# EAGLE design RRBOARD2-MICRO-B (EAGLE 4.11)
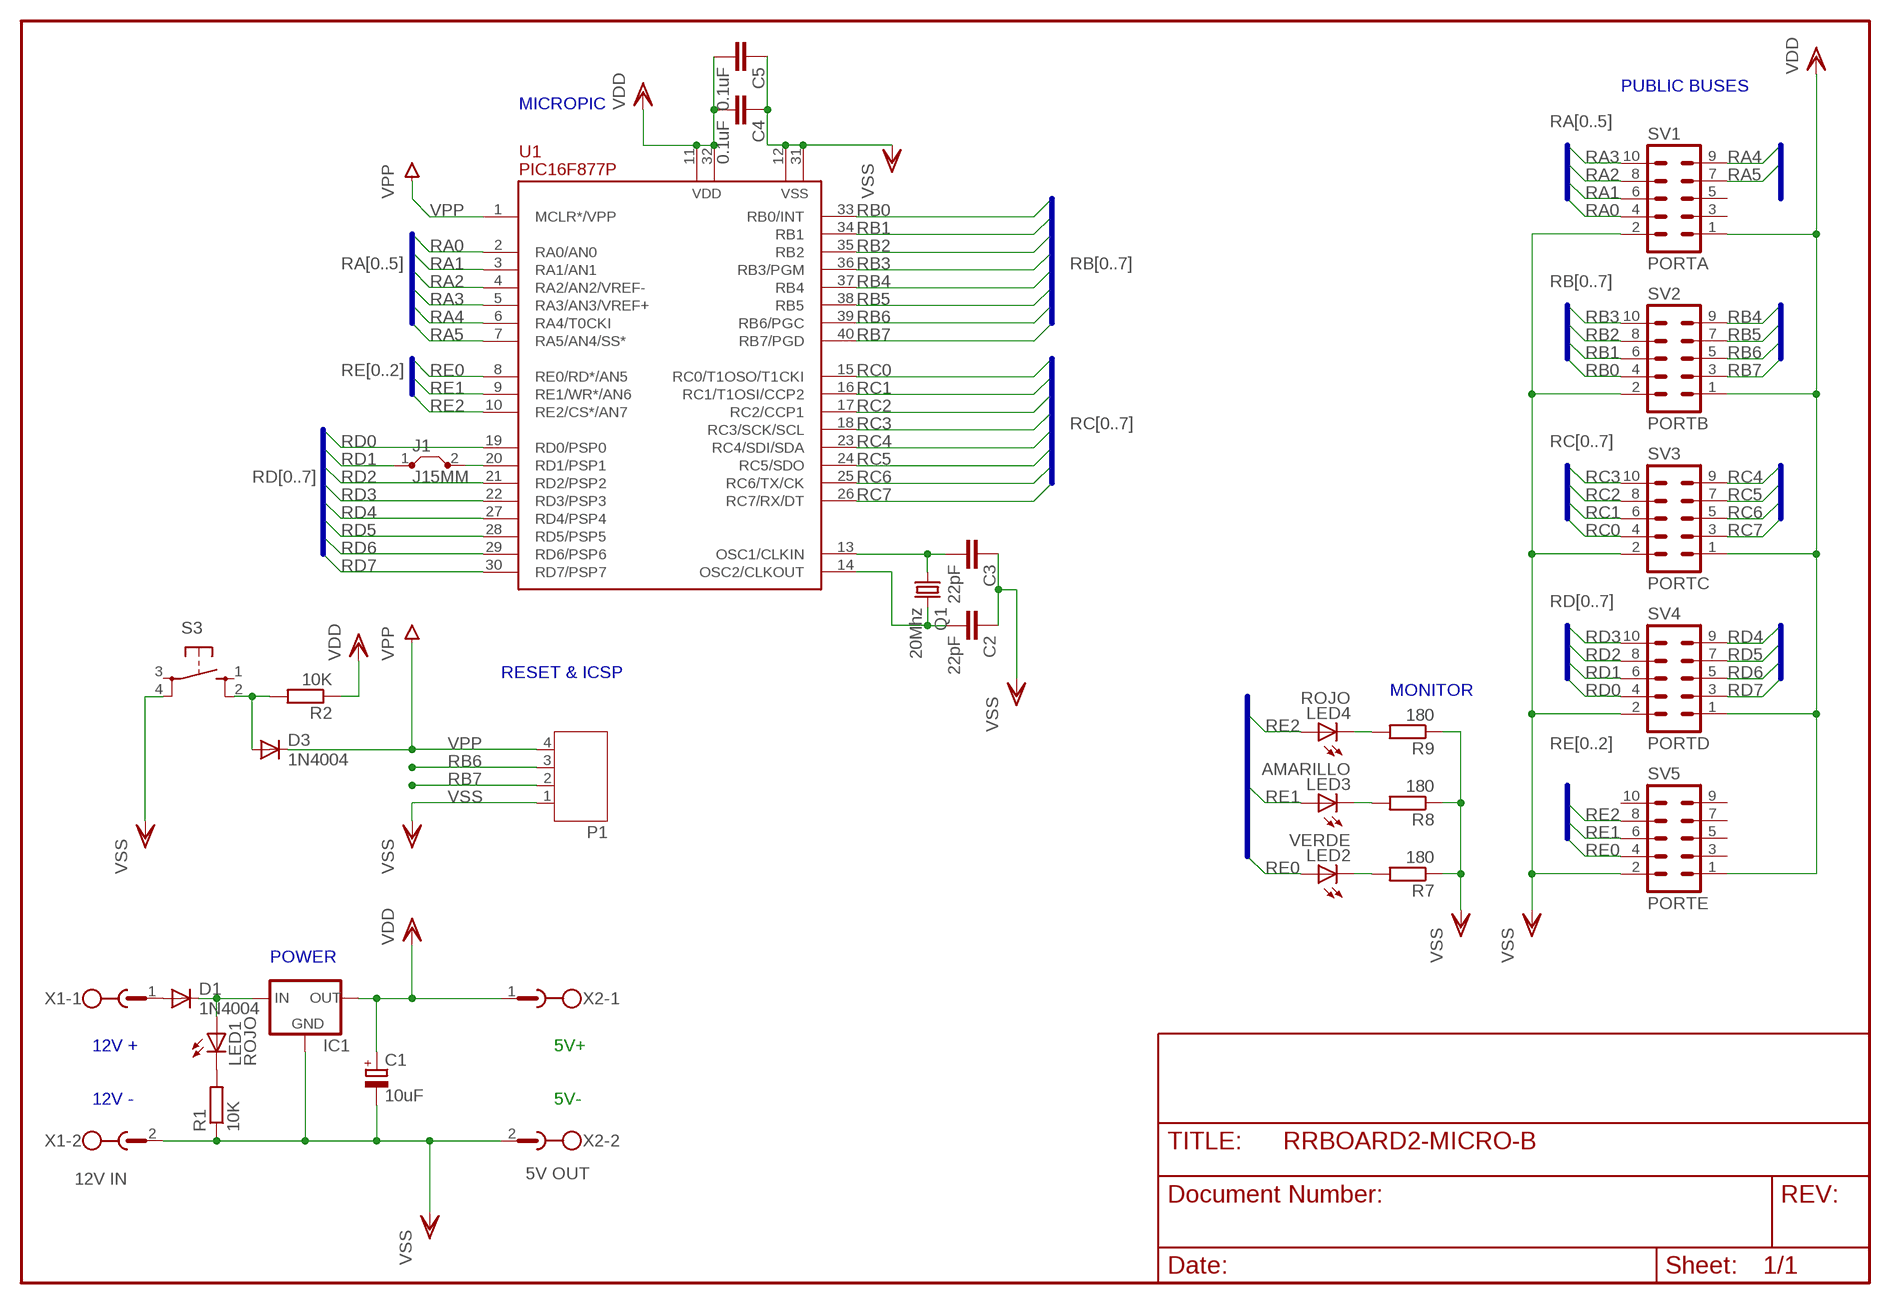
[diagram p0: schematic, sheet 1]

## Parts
C1  10uF  CPOL-EUB45181B  [B45181B]
C2  22pF  C-EU025-030X050  [C025-030X050]
C3  22pF  C-EU025-030X050  [C025-030X050]
C4  0.1uF  C-EU025-025X050  [C025-025X050]
C5  0.1uF  C-EU025-025X050  [C025-025X050]
D1  1N4004  [DO41-10]
D3  1N4004  [DO41-10]
IC1  78XXL  [78XXL]
J1  J15MM  [15]
LED1  ROJO  LED5MM  [LED5MM]
LED2  VERDE  LED5MM  [LED5MM]
LED3  AMARILLO  LED5MM  [LED5MM]
LED4  ROJO  LED5MM  [LED5MM]
P1  JST-PH_JST-PH4  [JST-PH_JST-PH4]
Q1  20Mhz  CRYTALHC49S  [HC49/S]
R1  10K  R-EU_0204/5  [0204/5]
R2  10K  R-EU_0204/5  [0204/5]
R7  180  R-EU_0204/5  [0204/5]
R8  180  R-EU_0204/5  [0204/5]
R9  180  R-EU_0204/5  [0204/5]
S3  10XX  [B3F-10XX]
SV1  PORTA  ML10  [ML10]
SV2  PORTB  ML10  [ML10]
SV3  PORTC  ML10  [ML10]
SV4  PORTD  ML10  [ML10]
SV5  PORTE  ML10  [ML10]
U1  PIC16F877P  [DIL40]
X1  12V IN  MSTBA2  [MSTBA2]
X2  5V OUT  MSTBA2  [MSTBA2]

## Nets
N$1: D1.A X1.1
N$4: LED1.K(C) R1.2
OSC1: C3.2 Q1.1 U1.13(OSC1/CLKIN)
OSC2: C2.2 Q1.2 U1.14(OSC2/CLKOUT)
RA0: SV1.4 U1.2(RA0/AN0)
RA1: SV1.6 U1.3(RA1/AN1)
RA2: SV1.8 U1.4(RA2/AN2/VREF-)
RA3: SV1.10 U1.5(RA3/AN3/VREF+)
RA4: SV1.9 U1.6(RA4/T0CKI)
RA5: SV1.7 U1.7(RA5/AN4/SS*)
RB0: SV2.4 U1.33(RB0/INT)
RB1: SV2.6 U1.34(RB1)
RB2: SV2.8 U1.35(RB2)
RB3: SV2.10 U1.36(RB3/PGM)
RB4: SV2.9 U1.37(RB4)
RB5: SV2.7 U1.38(RB5)
RB6: P1.3 SV2.5 U1.39(RB6/PGC)
RB7: P1.2 SV2.3 U1.40(RB7/PGD)
RC0: SV3.4 U1.15(RC0/T1OSO/T1CKI)
RC1: SV3.6 U1.16(RC1/T1OSI/CCP2)
RC2: SV3.8 U1.17(RC2/CCP1)
RC3: SV3.10 U1.18(RC3/SCK/SCL)
RC4: SV3.9 U1.23(RC4/SDI/SDA)
RC5: SV3.7 U1.24(RC5/SDO)
RC6: SV3.5 U1.25(RC6/TX/CK)
RC7: SV3.3 U1.26(RC7/RX/DT)
RD0: SV4.4 U1.19(RD0/PSP0)
RD1: J1.1 SV4.6
RD1X: J1.2 U1.20(RD1/PSP1)
RD2: SV4.8 U1.21(RD2/PSP2)
RD3: SV4.10 U1.22(RD3/PSP3)
RD4: SV4.9 U1.27(RD4/PSP4)
RD5: SV4.7 U1.28(RD5/PSP5)
RD6: SV4.5 U1.29(RD6/PSP6)
RD7: SV4.3 U1.30(RD7/PSP7)
RE0: LED2.A SV5.4 U1.8(RE0/RD*/AN5)
RE1: LED3.A SV5.6 U1.9(RE1/WR*/AN6)
RE2: LED4.A SV5.8 U1.10(RE2/CS*/AN7)
RRE0: LED2.K(C) R7.2
RRE1: LED3.K(C) R8.2
RRE2: LED4.K(C) R9.2
RST1: D3.A R2.2 S3.2
V12P: D1.C IC1.IN LED1.A
VDD: C1.+ C4.2 C5.2 IC1.OUT R2.1 SV1.1 SV2.1 SV3.1 SV4.1 SV5.1 U1.11(VDD) U1.32(VDD) X2.1
VPP: D3.C P1.4 U1.1(MCLR*/VPP)
VSS: C1.- C2.1 C3.1 C4.1 C5.1 IC1.GND P1.1 R1.1 R7.1 R8.1 R9.1 S3.4 SV1.2 SV2.2 SV3.2 SV4.2 SV5.2 U1.12(VSS) U1.31(VSS) X1.2 X2.2
Unconnected: S3.1 S3.3 SV1.3 SV1.5 SV5.3 SV5.5 SV5.7 SV5.9 SV5.10

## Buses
RE[0..2]
RD[0..7]
RA[0..5]
RB[0..7]
RC[0..7]

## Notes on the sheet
- PUBLIC BUSES
- MICROPIC
- RESET & ICSP
- MONITOR
- POWER
- 12V + | 5V+
- 12V - | 5V-

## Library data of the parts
C1 = rcl:CPOL-EU: POLARIZED CAPACITOR, European symbol
C2-C5 = rcl:C-EU: CAPACITOR, European symbol
D1 D3 = diode:1N4004: DIODE
IC1 = v-reg:78XXL: VOLTAGE REGULATOR
J1 = jumper:J: Bridge
LED1-LED4 = led:LED: LED
P1 = 000_REDPIC:JST-PH_JST-PH4
Q1 = crystal:CRYTAL: CRYSTAL
R1 R2 R7-R9 = rcl:R-EU_: RESISTOR, European symbol
S3 = KEY_B:10XX
SV1-SV5 = con-ml:ML10: HARTING
U1 = microchip-pic16f87x:PIC16F877: FLASH MICROCONTROLLER
X1 X2 = con-phoenix-508:MSTBA2: PHOENIX

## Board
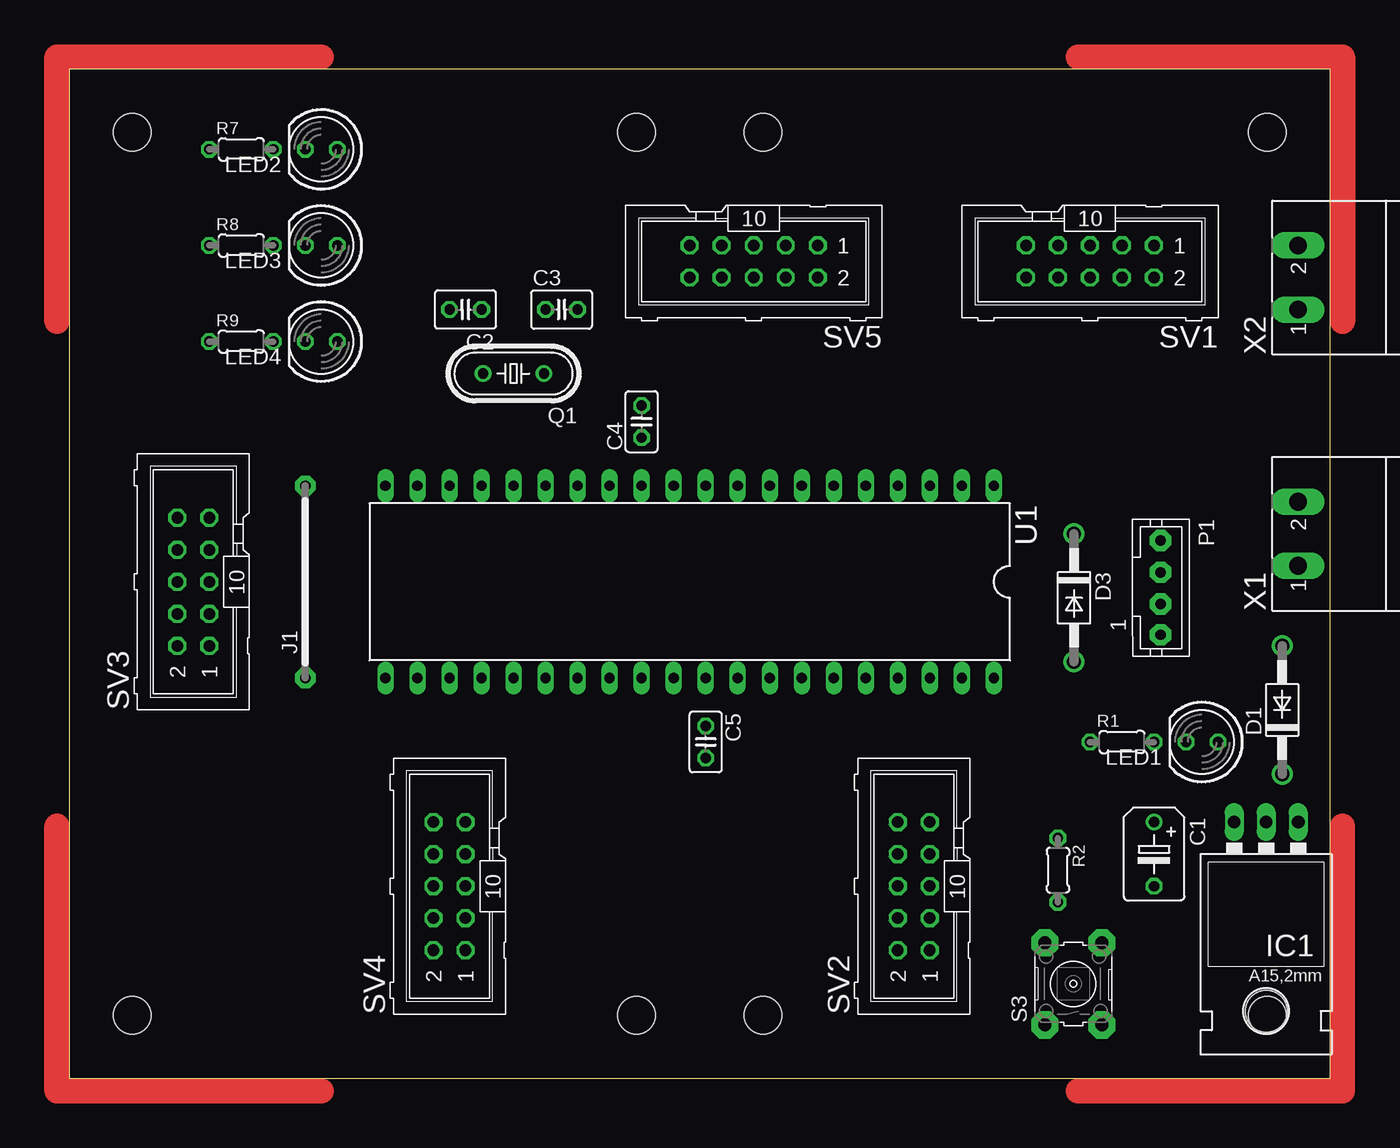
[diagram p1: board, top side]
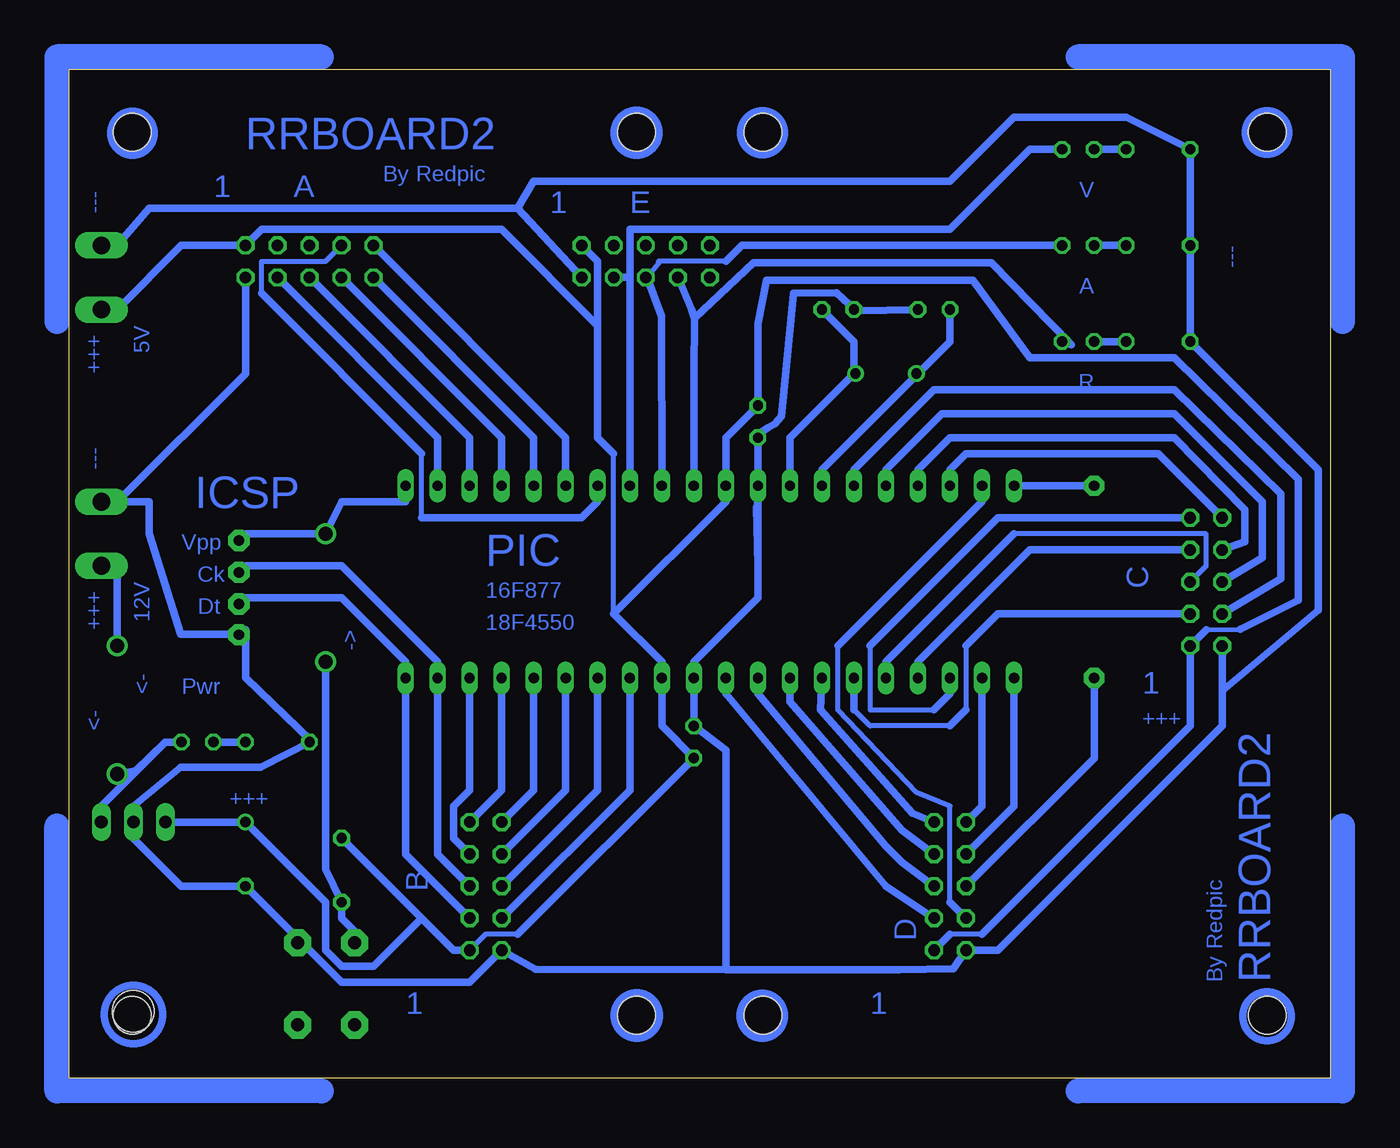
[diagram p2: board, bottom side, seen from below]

Size 100 x 80 mm. Coordinates in mm from the lower left corner, seen from the top.
Outline: 100,0 100,80 0,80 0,0 100,0
Copper layers (1*16): Top 0.035mm / dielectric 1.5mm / Bottom 0.035mm
Design rules "default": minimum track width 10mil, minimum drill 24mil, track to track 8mil, track to pad 8mil, pad to pad 8mil, via to via 8mil, smd to smd 8mil, copper to edge 40mil, drill to drill 8mil, minimum pad ring 10mil, minimum via ring 8mil, stop-mask expansion 4mil, vias tented up to drill 0mil, thermal gap 10mil
Holes 3 mm at 95,5 95,75 5,5 5,75 55,5 45,5 55,75 45,75

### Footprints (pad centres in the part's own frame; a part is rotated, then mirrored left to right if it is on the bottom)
B45181B = drill 0.813 round: + -2.54,0 | drill 0.813 octagon: - 2.54,0
C025-030X050 = drill 0.813 octagon: 1 -1.27,0; 2 1.27,0
C025-025X050 = drill 0.813 octagon: 1 -1.27,0; 2 1.27,0
DO41-10 = drill 1.118 round: A 5.08,0; C -5.08,0
78XXL = drill 1.016 long: GND 0,-3.81; IN -2.54,-3.81; OUT 2.54,-3.81 | hole 3.302: 0,11.176
15 = drill 0.813 pad 1.6 octagon: 1 -7.62,0; 2 7.62,0
LED5MM = drill 0.813 octagon: A -1.27,0; K 1.27,0
JST-PH_JST-PH4 = drill 0.813 pad 1.676 octagon: 1 4.194,0.525; 2 1.754,0.517; 3 -0.749,0.525; 4 -3.275,0.525
HC49/S = drill 0.813 round: 1 -2.413,0; 2 2.413,0
0204/5 = drill 0.813 octagon: 1 -2.54,0; 2 2.54,0
B3F-10XX = drill 1.016 pad 2.159 octagon: 1 -3.379,2.312; 2 3.123,2.312; 3 -3.379,-2.209; 4 3.123,-2.209
ML10 = drill 0.914 octagon: 1 -5.08,-1.27; 2 -5.08,1.27; 3 -2.54,-1.27; 4 -2.54,1.27; 5 0,-1.27; 6 0,1.27; 7 2.54,-1.27; 8 2.54,1.27; 9 5.08,-1.27; 10 5.08,1.27
DIL40 = drill 0.813 long: 1 -24.13,-7.62; 2 -21.59,-7.62; 3 -19.05,-7.62; 4 -16.51,-7.62; 5 -13.97,-7.62; 6 -11.43,-7.62; 7 -8.89,-7.62; 8 -6.35,-7.62; 9 -3.81,-7.62; 10 -1.27,-7.62; 11 1.27,-7.62; 12 3.81,-7.62; 13 6.35,-7.62; 14 8.89,-7.62; 15 11.43,-7.62; 16 13.97,-7.62; 17 16.51,-7.62; 18 19.05,-7.62; 19 21.59,-7.62; 20 24.13,-7.62; 21 24.13,7.62; 22 21.59,7.62; 23 19.05,7.62; 24 16.51,7.62; 25 13.97,7.62; 26 11.43,7.62; 27 8.89,7.62; 28 6.35,7.62; 29 3.81,7.62; 30 1.27,7.62; 31 -1.27,7.62; 32 -3.81,7.62; 33 -6.35,7.62; 34 -8.89,7.62; 35 -11.43,7.62; 36 -13.97,7.62; 37 -16.51,7.62; 38 -19.05,7.62; 39 -21.59,7.62; 40 -24.13,7.62
MSTBA2 = drill 1.397 long: 1 -2.54,5.08; 2 2.54,5.08

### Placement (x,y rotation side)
C1  86.03,17.78 270 top
C2  31.42,60.96 180 top
C3  39.04,60.96 0 top
C4  45.39,52.07 90 top
C5  50.47,26.67 270 top
D1  96.19,29.21 90 top
D3  79.68,38.1 270 top
IC1  94.92,16.51 180 top
J1  18.72,39.37 90 top
LED1  89.84,26.67 180 top
LED2  19.99,73.66 180 top
LED3  19.99,66.04 180 top
LED4  19.99,58.42 180 top
P1  86.03,39.37 270 top
Q1  35.23,55.88 180 top
R1  83.49,26.67 0 top
R2  78.41,16.51 270 top
R7  13.64,73.66 0 top
R8  13.64,66.04 0 top
R9  13.64,58.42 0 top
S3  79.68,7.62 90 top
SV1  80.95,64.77 180 top
SV2  66.98,15.24 90 top
SV3  9.83,39.37 90 top
SV4  30.15,15.24 90 top
SV5  54.28,64.77 180 top
U1  49.2,39.37 180 top
X1  102.54,43.18 90 top
X2  102.54,63.5 90 top

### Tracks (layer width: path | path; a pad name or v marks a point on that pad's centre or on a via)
N$1
  Bottom 0.61: D1.A 96.19,40.64 X1.1
N$2
  Top 2: 101,20 101,-1 80,-1
N$3
  Top 2: 101,60 101,81 80,81
N$4
  Bottom 0.61: R1.2 LED1.K
N$5
  Top 2: -1,20 -1,-1 20,-1
N$6
  Top 2: 20,81 -1,81 -1,60
N$7
  Bottom 2: 101,20 101,-1 80,-1
N$8
  Bottom 2: 101,60 101,81 80,81
N$9
  Bottom 2: -1,20 -1,-1 20,-1
N$10
  Bottom 2: 20,81 -1,81 -1,60
OSC1
  Bottom 0.61: 37.77,55.88 37.77,58.42 C3.2 | 37.77,55.88 42.85,50.8 U1.13 | 37.77,55.88 Q1.1
OSC2
  Bottom 0.61: 32.69,55.88 40.31,48.26 U1.14 | C2.2 30.15,58.42 32.69,55.88 | 32.69,55.88 Q1.2
RA0
  Bottom 0.61: SV1.4 70.79,50.8 U1.2
RA1
  Bottom 0.61: SV1.6 68.25,50.8 U1.3
RA2
  Bottom 0.61: SV1.8 65.71,50.8 U1.4
RA3
  Bottom 0.61: SV1.10 63.17,50.8 U1.5
RA4
  Bottom 0.61: SV1.9 60.63,50.8 U1.6
RA5
  Bottom 0.406: 72.06,44.45 72.06,49.53 | 84.76,62.23 84.76,64.77 79.68,64.77 SV1.7
  Bottom 0.61: 72.06,44.45 59.36,44.45 58.09,45.72 U1.7 | 72.06,49.53 84.76,62.23
RB0
  Bottom 0.61: SV2.4 55.55,22.86 U1.33
RB1
  Bottom 0.61: SV2.6 58.09,22.86 U1.34
RB2
  Bottom 0.61: SV2.8 60.63,22.86 U1.35
RB3
  Bottom 0.61: SV2.10 63.17,22.86 U1.36
RB4
  Bottom 0.61: SV2.9 65.71,22.86 U1.37
RB5
  Bottom 0.61: SV2.7 69.52,19.05 69.52,21.59 68.25,22.86 U1.38
RB6
  Bottom 0.61: SV2.5 70.79,17.78 U1.39 70.79,33.02 78.41,40.64 86.03,40.64 P1.3
RB7
  Bottom 0.61: SV2.3 73.33,17.78 U1.40 73.33,33.02 78.41,38.1 86.03,38.1 P1.2
RC0
  Bottom 0.61: SV3.4 3.91,39.61 3.91,46.36 12.37,54.61 31.42,54.61 37.77,48.26 U1.15
RC1
  Bottom 0.61: SV3.6 5.38,41.28 5.38,45.72 12.37,52.71 30.79,52.71 35.23,48.26 U1.16
RC2
  Bottom 0.61: SV3.8 6.77,42.56 6.77,45.1 12.37,50.8 30.15,50.8 32.69,48.26 U1.17
RC3
  Bottom 0.61: SV3.10 13.64,49.53 28.88,49.53 30.15,48.26 U1.18
RC4
  Bottom 0.406: 31.42,29.21 36.5,29.21 36.5,34.29
  Bottom 0.61: 31.42,29.21 30.15,30.48 U1.23 | 36.5,34.29 26.34,44.45 SV3.9
RC5
  Bottom 0.61: SV3.7 23.8,41.91 32.69,33.02 U1.24
RC6
  Bottom 0.406: 25.07,43.18 9.83,43.18 9.83,40.64 SV3.5
  Bottom 0.61: 25.07,43.18 35.23,33.02 U1.25
RC7
  Bottom 0.406: 37.77,29.21 36.5,27.94 30.15,27.94 | 28.88,34.29 28.88,29.21
  Bottom 0.61: 28.88,29.21 30.15,27.94 | 28.88,34.29 26.34,36.83 SV3.3 | 37.77,29.21 U1.26
RD0
  Bottom 0.406: 39.04,34.29 39.04,29.21 32.78,22.66 30.15,21.59 30.15,13.97
  Bottom 0.61: 39.04,34.29 27.61,45.72 U1.19 | SV4.4 30.15,13.97
RD1
  Bottom 0.61: SV4.6 18.72,25.4 J1.1
RD1X
  Bottom 0.61: J1.2 U1.20
RD2
  Bottom 0.61: SV4.8 25.07,21.59 U1.21
RD3
  Bottom 0.61: SV4.10 27.61,21.59 U1.22
RD4
  Bottom 0.61: SV4.9 33.13,21.02 33.77,21.72 40.41,29.21 U1.27
RD5
  Bottom 0.61: SV4.7 33.96,19.68 42.85,29.84 U1.28
RD6
  Bottom 0.61: SV4.5 33.96,17.14 35.23,18.41 45.39,30.48 U1.29
RD7
  Bottom 0.61: SV4.3 35.23,15.24 47.93,30.48 U1.30
RE0
  Bottom 0.61: LED2.A 23.8,73.66 30.15,67.31 55.55,67.31 55.55,63.5 | 55.55,63.5 U1.8 | 55.55,63.5 SV5.4
RE1
  Bottom 0.406: 47.93,64.77 53.31,64.78 53.13,64.78 54.2,63.52 SV5.6
  Bottom 0.61: LED3.A 46.66,66.04 47.93,64.77 | 54.2,63.52 53.02,60.44 U1.9
RE2
  Bottom 0.61: LED4.A 20.53,58.16 26.88,64.66 45.74,64.66 50.43,60.25 | 50.43,60.25 50.47,55.88 U1.10 | SV5.8 50.65,60.97 50.43,60.25
RRE0
  Bottom 0.61: R7.2 LED2.K
RRE1
  Bottom 0.61: R8.2 LED3.K
RRE2
  Bottom 0.61: R9.2 LED4.K
RST1
  Bottom 0.61: S3.2 77.14,11.43 78.41,12.7 R2.2 79.68,16.57 79.68,27.94 79.66,29.21 D3.A
V12P
  Bottom 0.61: 92.38,26.67 94.72,24.38 D1.C | LED1.A 92.38,26.67 | 92.38,26.67 97.46,21.59 IC1.IN
VDD
  Bottom 0.406: 27.61,11.43 30.15,11.43 | 56.82,36.83 56.82,49.53 | SV2.1 66.98,11.43 64.44,11.43 | 9.83,35.56 7.11,35.6
  Bottom 0.61: 27.61,11.43 11.1,27.94 SV3.1 9.83,35.56 | 30.15,11.43 SV4.1 | IC1.OUT C1.+ 79.68,13.97 79.68,10.16 78.41,8.89 75.87,8.89 72.06,12.7 | 72.06,12.7 69.52,10.16 SV2.1 | 72.06,12.7 R2.1 | X2.1 96.19,60.96 91.11,66.04 SV1.1 84.76,67.31 65.71,67.31 58.09,59.69 | SV5.1 58.09,64.77 58.09,59.69 | 58.09,59.69 58.09,50.8 56.82,49.53 | 64.44,11.43 C5.2 53.01,27.94 U1.32 53.01,33.02 56.82,36.83 47.93,45.72 U1.11 47.93,50.8 C4.2 45.39,59.81 44.72,63.28 28.33,63.28 23.8,57.15 12.37,57.15 2.54,47.52 2.54,37.93 7.11,35.6
VPP
  Bottom 0.61: U1.1 73.33,45.72 78.41,45.72 D3.C 86.03,43.18 P1.4
VSS
  Bottom 0.406: 45.5,45.28 45.38,51.08 45.12,50.55
  Bottom 0.61: 37.61,60.88 C3.1 | 37.61,60.88 C2.1 | C4.1 U1.12 45.39,40.64 | 45.39,40.64 45.39,38.1 50.47,33.02 U1.31 C5.1 47.93,26.04 47.93,8.63 | 37.61,60.88 39.15,62.29 42.58,62.27 42.57,62.23 43.54,52.49 44.05,51.89 44.59,51.6 45.38,51.08 | 45.39,40.64 45.5,45.28 | 80.79,26.72 86.03,31.75 86.03,35.56 P1.1 87.34,35.2 91.15,35.2 93.65,43.18 93.65,45.72 X1.2 96.19,45.72 86.03,55.88 SV1.2 | 80.79,26.72 R1.1 | 80.79,26.72 84.83,24.68 91.18,24.68 94.92,21.59 IC1.GND 94.92,19.05 91.11,15.24 C1.- 82.22,11.43 S3.4 80.95,10.16 78.41,7.62 68.25,7.62 SV2.2 63.03,8.65 47.93,8.63 | 64.44,68.99 SV5.2 | 64.44,68.99 93.65,68.99 96.19,66.04 X2.2 | 8.56,30.75 8.56,27.94 26.34,10.16 SV4.2 29.86,8.68 34.16,8.62 47.93,8.63 | 8.56,30.75 SV3.2 | 8.56,30.75 0.94,37.1 0.94,48.26 R9.1 R8.1 R7.1 16.18,76.2 25.07,76.2 30.15,71.12 63.17,71.12 64.44,68.99
(copper drawn outside any net)
  shapes: Bottom circle x8

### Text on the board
Bottom: RRBOARD2 | By Redpic | V | A | 1 | E | 1 | --- | --- | A | 5V | R | +++ | --- | ICSP | Vpp | C | PIC | Ck | 12V | 16F877 | Dt | 18F4550 | -> | +++ | 1 | Pwr | <- | <- | +++ | +++ | B | D | RRBOARD2 | By Redpic | 1 | 1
